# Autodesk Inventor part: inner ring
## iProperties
Created: 2009-01
Part Number: inner ring
Document SubType Name: Modeling
Designer: pmulligan
Density: 1 g/cm^3
Author: pmulligan
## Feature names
1. Revolution1
2. Chamfer1
3. Chamfer2
